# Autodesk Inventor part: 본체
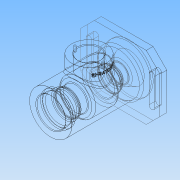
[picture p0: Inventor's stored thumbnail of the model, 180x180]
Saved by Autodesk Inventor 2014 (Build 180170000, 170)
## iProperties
Created: 2017-10
Part Number: 본체
Material: 일반
Document SubType Name: Modeling
Designer: net
Density: 1 g/cm^3
Appearance: 기본값
Mass: 271.768 g
Surface Area: 655.302 cm^2
Volume: 271.768 cm^3
Author: net
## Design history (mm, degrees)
sketch "스케치1"
  geometry: L1 (-58, 47)-(58, 47); L2 (58, 47)-(58, -47); L3 (58, -47)-(-58, -47); L4 (-58, -47)-(-58, 47); C1 r 31 at (0, 0); 3 further points
  constraints: 8 end point, 2 midpoint, 2 parallel, 1 centre point, 1 coincident, 1 horizontal, 1 horizontal alignment, 1 perpendicular, 1 vertical alignment
  dimensions: "d0" = 62 diameter of C1; "d3" = 116 distance of L2.end L3.end; "d4" = 94 distance of L3.end L1.start
extrude "돌출1" new body sketch "스케치1" distance "d5" = 102; taper "d6" = 0 deg; dims "d9" = 10, "d10" = 0
extrude "돌출2" join sketch "스케치1" distance "d7" = 10; taper "d8" = 0 deg
sketch "스케치2"
  geometry: L1 (58, 47)-(-58, 47) reference; L2 (58, -47)-(58, 47) reference; C1 r 35 at (0, 0); 3 further points
  constraints: 2 midpoint, 1 centre point, 1 horizontal alignment, 1 vertical alignment
  dimensions: "d11" = 70 diameter of C1
extrude "돌출3" join sketch "스케치2" distance "d12" = 3; taper "d13" = 0 deg
sketch "스케치3"
  geometry: L1 (31, 102)-(-31, 102) reference; L2 (-35, -13)-(35, -13) reference; L3 (0, 102)-(0, -13); L4 (21, 102)-(21, 93); L5 (21, 93)-(24, 93); L6 (24, 93)-(24, 90); L7 (24, 90)-(20, 90); L8 (20, 90)-(20, 81); L9 (20, 81)-(17.5, 81); L10 (17.5, 81)-(17.5, 77.75); L11 (17.5, 77.75)-(18.5, 77.75); L12 (18.5, 77.75)-(18.5, 76); L13 (18.5, 76)-(17.5, 76); L14 (17.5, 76)-(17.5, 65); L15 (17.5, 65)-(26, 65); L16 (26, 65)-(26, 27); L17 (26, 27)-(17.5, 27); L18 (17.5, 27)-(17.5, 16); L19 (17.5, 16)-(16.5, 16); L20 (16.5, 16)-(16.5, 11); L21 (16.5, 11)-(10, 11); L22 (10, 11)-(10, 8.3); L23 (10, 8.3)-(12.5, 8.3); L24 (12.5, 8.3)-(12.5, 1); L25 (12.5, 1)-(16, 1); L26 (16, 1)-(22, -13); 1 further point
  constraints: 48 end point, 17 parallel, 5 perpendicular, 2 midpoint, 2 point on line, 1 collinear
  dimensions: "d14" = 52 diameter of L16 L3; "d15" = 35 diameter of L14 L3; "d16" = 42 diameter of L4 L3; "d17" = 48 diameter of L6 L3; "d18" = 40 diameter of L8 L3; "d19" = 35 diameter of L10 L3; "d20" = 37 diameter of L12 L3; "d21" = 33 diameter of L20 L3; "d22" = 20 diameter of L22 L3; "d24" = 25 diameter of L24 L3; "d25" = 32 diameter of L25.end L3; "d26" = 44 diameter of L26.end L3; "d27" = 12 distance between parallel lines of L7 L1; "d28" = 3 distance of L5.end L6.end; "d29" = 21 distance between parallel lines of L1 L9; "d30" = 26 distance between parallel lines of L1 L13; "d31" = 1.75 distance of L11.end L12.end; "d32" = 11 distance of L13.end L14.end; "d33" = 38 distance of L15.end L16.end; "d34" = 11 distance of L17.end L18.end; "d35" = 14 distance between parallel lines of L25 L2; "d37" = 7.3 distance of L23.end L24.end; "d38" = 2.7 distance of L21.end L22.end
revolve "회전1" sketch "스케치3" stored, may be unused: angle "d39" = 90 deg
chamfer "모따기1" distance "d40" = 0.7; stored, may be unused: second distance "d41" = 2, angle "d42" = 30 deg
fillet "모깎기1" dims "d43" = 0.3
fillet "모깎기2" dims "d44" = 0.3
feature "스레드1" dims "d45" = 10, "d46" = 0
chamfer "모따기2" distance "d47" = 1; stored, may be unused: second distance "d48" = 2, angle "d49" = 30 deg
sketch "스케치4"
  geometry: L1 (0, 0)-(116, 0) reference; L2 (27, -102)-(89, -102) reference; C1 r 25 at (58, -46); 2 further points
  constraints: 1 centre point, 1 midpoint, 1 vertical alignment
  dimensions: "d50" = 50 diameter of C1; "d51" = 56 distance from line of L2 C1.centre
extrude "돌출4" join sketch "스케치4" stored distance "d52" = 3; taper "d53" = 0 deg
hole "구멍1" diameter "d56" = 32; stored, may be unused: countersink angle "d60" = 90 deg, drill point angle "d62" = 118 deg; dims "d54" = 10, "d55" = 10, "d57" = 6, "d58" = 4, "d59" = 2, "d61" = 34.75
chamfer "모따기3" distance "d63" = 1; stored, may be unused: second distance "d64" = 2, angle "d65" = 30 deg
sketch "스케치5"
  geometry: L1 (-58, -47)-(-58, 47) reference; L2 (46, 20)-(46, -20); L3 (42, 20)-(42, -20); L4 (50, -20)-(50, 20); C1 r 31 at (0, 0) reference; A1 r 4 centre (46, 20) between (50, 20) and (42, 20); A2 r 4 centre (46, -20) between (42, -20) and (50, -20); 1 further point
  constraints: 8 end point, 4 point on circle, 4 tangent, 2 centre point, 2 parallel, 1 horizontal alignment, 1 midpoint
  dimensions: "d66" = 46 distance of point (46, 0) C1.centre; "d67" = 40 distance of L2.end L2.start; "d68" = 4 radius of A1
extrude "돌출5" cut sketch "스케치5" stored distance "d69" = 3; taper "d70" = 0 deg
chamfer "모따기4" distance "d71" = 20; stored, may be unused: second distance "d72" = 2, angle "d73" = 30 deg
fillet "모깎기3" dims "d74" = 3
fillet "모깎기4" dims "d75" = 3
sketch "스케치6"
  geometry: C1 r 25 at (0, 0) reference; 2 further points
  constraints: 1 horizontal alignment
  dimensions: "d76" = 20.5 distance of point (-20.5, 0) C1.centre
hole "구멍2" sketch "스케치6" at (-20.5, 0) diameter "d77" = 2.459; stored, may be unused: countersink angle "d81" = 90 deg, drill point angle "d83" = 118 deg; dims "d78" = 6, "d79" = 4, "d80" = 2, "d82" = 8
fillet "모깎기5" dims "d87" = 3
node "작업 평면1"
sketch "스케치7"
  geometry: L1 (47, 71)-(47, 21) reference; L2 (31, 102)-(-31, 102) reference; 2 further points
  constraints: 1 other
  dimensions: "d89" = 10 distance from line of point (37, 46) L1; "d90" = 56 distance from line of L2 point (37, 46)
feature "엠보싱1" sketch "스케치7" dims "d91" = 0.5, "d92" = 0
fillet "모깎기6" dims "d93" = 3
node "솔리드1"
mirror "대칭1"
pattern_circular "원형 패턴1" dims angle "d85" = 360 deg
other parameters: "d88" = 31
